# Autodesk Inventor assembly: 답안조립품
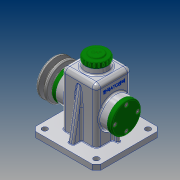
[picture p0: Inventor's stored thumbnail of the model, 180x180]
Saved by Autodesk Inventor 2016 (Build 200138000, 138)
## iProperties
Created: 2018-10
Part Number: 답안조립품
Material: 일반
Document SubType Name: Assembly
Designer: user
Author: user
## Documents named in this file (14)
- C:\Users\user\Desktop\481016V1010\답안조립품.iam
- C:\Users\user\Desktop\481016V1010\본체.ipt
- C:\Users\user\Desktop\481016V1010\뒤커버.ipt
- C:\Users\user\Desktop\481016V1010\앞커버.ipt
- C:\Users\user\Desktop\481016V1010\상부캡.ipt
- C:\Users\user\Desktop\481016V1010\오일실 15 25 7.ipt
- C:\Users\user\Desktop\481016V1010\축.ipt
- C:\Users\user\Desktop\481016V1010\멈춤링 15 x 1.ipt
- C:\Users\user\Desktop\481016V1010\베어링 15 x 35 x 11.ipt
- C:\Users\user\Desktop\481016V1010\키 5 x 5 x 14.ipt
- C:\Users\user\Desktop\481016V1010\V-벨트풀리.ipt
- C:\Users\user\Desktop\481016V1010\와셔.ipt
- C:\Users\user\Desktop\481016V1010\볼트 M6 x 12.ipt
- C:\Users\user\Desktop\481016V1010\볼트 M4 x 10.ipt
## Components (1 placed, 1 different names)
1. V-벨트풀리:1
